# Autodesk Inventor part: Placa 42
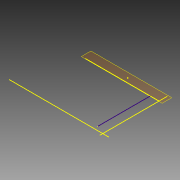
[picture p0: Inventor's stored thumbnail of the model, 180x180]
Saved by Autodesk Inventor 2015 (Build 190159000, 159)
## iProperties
Created: 2015-04
Part Number: Placa 42
Material: Generic
Document SubType Name: Modeling
Designer: suporte
Density: 1 g/cm^3
Appearance: Default
Author: suporte
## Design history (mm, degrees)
workplane "Work Plane1"
sketch "Sketch1"
  geometry: L1 (706.156, -1033.368)-(-993.844, -1033.368) reference; L2 (456.156, -970.868)-(456.156, -70.868) reference; L3 (-650.105, -70.868)-(606.156, -70.868) reference; L4 (456.156, -70.868)-(456.156, -970.868); L5 (606.156, 66.632)-(606.156, -1083.368) reference; L6 (456.156, -970.868)-(606.156, -970.868); L7 (606.156, -970.868)-(606.156, -70.868); L8 (606.156, -70.868)-(456.156, -70.868); 1 further point
  constraints: 8 end point, 2 collinear, 1 perpendicular, 1 point on line, 1 vertical
extrude "Extrusion1" new body sketch "Sketch1" distance "d0" = 12.5; taper "d1" = 0 deg
body "Solid1"
node "Reference1"
node "Reference2"
node "Reference3"
node "Reference4"
